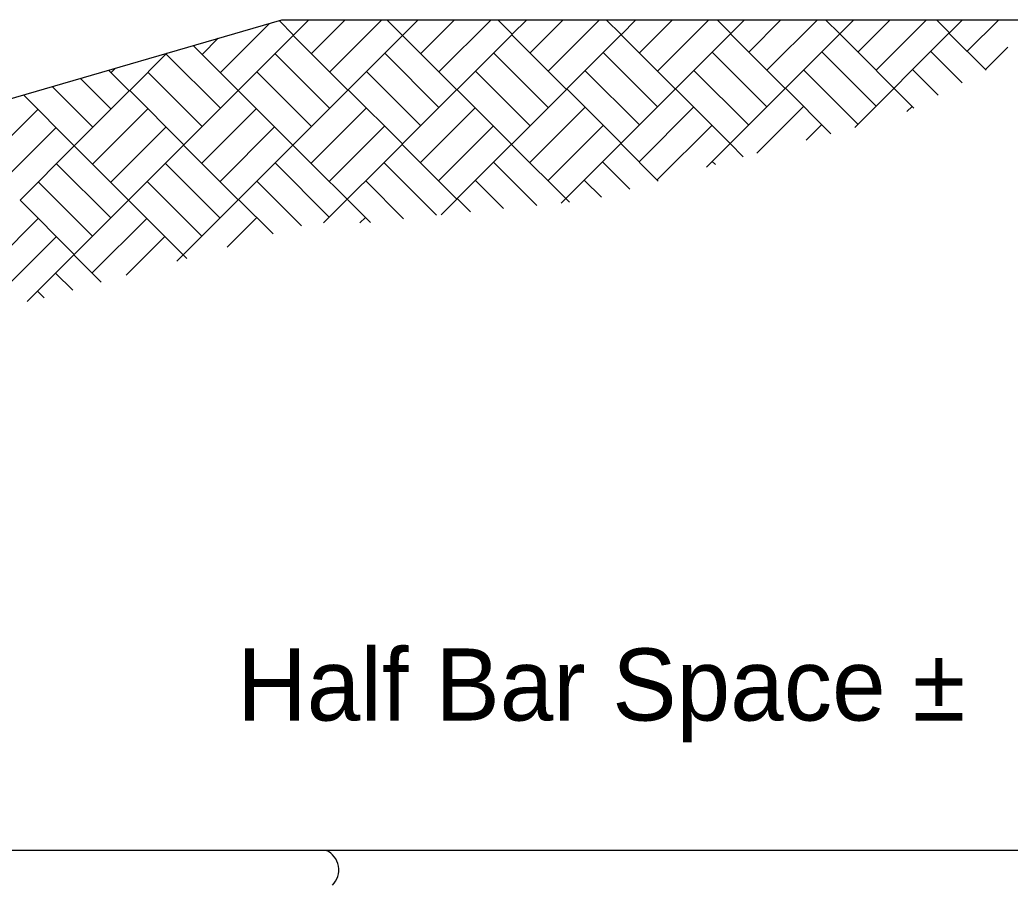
# Model space of a CAD drawing. Extents: x 0 to 221, y -2 to 90.
# Drawn here: x 46.22 to 54.52, y 25.31 to 32.56 of the extents above; entities that cross this region are included whole.
import ezdxf

# ---------------------------------------------------------------- set-up
doc = ezdxf.new("R2010")
doc.units = 0
for name, color, linetype in [('AdhocPoint_dp', 7, 'Continuous'), ('Border', 7, 'Continuous'), ('Miscellaneous', 7, 'Continuous'), ('PlotBorder_dp', 7, 'Continuous'), ('WallConc', 7, 'Continuous')]:
    doc.layers.add(name, color=color, linetype=linetype)

msp = doc.modelspace()

# ---------------------------------------------------------------- linework, layer by layer
at = {"layer": 'Border'}
for p, q in [((48.6425, 32.5647), (48.5146, 32.4368)), ((48.6425, 32.5647), (48.5146, 32.4368)), ((48.6425, 32.5647), (48.5146, 32.4368)), ((48.948, 32.5647), (48.6673, 32.2841)), ((48.948, 32.5647), (48.6673, 32.2841)), ((48.948, 32.5647), (48.6673, 32.2841)), ((49.2534, 32.5647), (48.82, 32.1313)), ((49.2534, 32.5647), (48.82, 32.1313)), ((49.2534, 32.5647), (48.82, 32.1313)), ((49.4279, 32.4337), (49.297, 32.5647)), ((49.4279, 32.4337), (49.297, 32.5647)), ((49.4279, 32.4337), (49.297, 32.5647)), ((49.5591, 32.5647), (49.428, 32.4336)), ((49.5591, 32.5647), (49.428, 32.4336)), ((49.5591, 32.5647), (49.428, 32.4336)), ((49.8646, 32.5647), (49.5808, 32.2809)), ((49.8646, 32.5647), (49.5808, 32.2809)), ((49.8646, 32.5647), (49.5808, 32.2809)), ((50.17, 32.5647), (49.7335, 32.1282)), ((50.17, 32.5647), (49.7335, 32.1282)), ((50.17, 32.5647), (49.7335, 32.1282)), ((50.3479, 32.4432), (50.2264, 32.5647)), ((50.3479, 32.4432), (50.2264, 32.5647)), ((50.3479, 32.4432), (50.2264, 32.5647)), ((50.4694, 32.5647), (50.3479, 32.4432)), ((50.4694, 32.5647), (50.3479, 32.4432)), ((50.4694, 32.5647), (50.3479, 32.4432)), ((50.7749, 32.5647), (50.5006, 32.2905)), ((50.7749, 32.5647), (50.5006, 32.2905)), ((50.7749, 32.5647), (50.5006, 32.2905)), ((51.0803, 32.5647), (50.6533, 32.1377)), ((51.0803, 32.5647), (50.6533, 32.1377)), ((51.0803, 32.5647), (50.6533, 32.1377)), ((51.2612, 32.4401), (51.1367, 32.5647)), ((51.2612, 32.4401), (51.1367, 32.5647)), ((51.2612, 32.4401), (51.1367, 32.5647)), ((51.386, 32.5647), (51.2613, 32.44)), ((51.386, 32.5647), (51.2613, 32.44)), ((51.386, 32.5647), (51.2613, 32.44)), ((51.6914, 32.5647), (51.4141, 32.2873)), ((51.6914, 32.5647), (51.4141, 32.2873)), ((51.6914, 32.5647), (51.4141, 32.2873)), ((51.9969, 32.5647), (51.5668, 32.1346)), ((51.9969, 32.5647), (51.5668, 32.1346)), ((51.9969, 32.5647), (51.5668, 32.1346)), ((52.1812, 32.4496), (52.0661, 32.5647)), ((52.1812, 32.4496), (52.0661, 32.5647)), ((52.1812, 32.4496), (52.0661, 32.5647)), ((52.2963, 32.5647), (52.1812, 32.4496)), ((52.2963, 32.5647), (52.1812, 32.4496)), ((52.2963, 32.5647), (52.1812, 32.4496)), ((52.6017, 32.5647), (52.3339, 32.2969)), ((52.6017, 32.5647), (52.3339, 32.2969)), ((52.6017, 32.5647), (52.3339, 32.2969)), ((52.9072, 32.5647), (52.4866, 32.1441)), ((52.9072, 32.5647), (52.4866, 32.1441)), ((52.9072, 32.5647), (52.4866, 32.1441)), ((53.0945, 32.4465), (52.9764, 32.5647)), ((53.0945, 32.4465), (52.9764, 32.5647)), ((53.0945, 32.4465), (52.9764, 32.5647)), ((53.2129, 32.5647), (53.0946, 32.4464)), ((53.2129, 32.5647), (53.0946, 32.4464)), ((53.2129, 32.5647), (53.0946, 32.4464)), ((53.5183, 32.5647), (53.2474, 32.2937)), ((53.5183, 32.5647), (53.2474, 32.2937)), ((53.5183, 32.5647), (53.2474, 32.2937)), ((53.8238, 32.5647), (53.4001, 32.141)), ((53.8238, 32.5647), (53.4001, 32.141)), ((53.8238, 32.5647), (53.4001, 32.141)), ((54.0145, 32.456), (53.9058, 32.5647)), ((54.0145, 32.456), (53.9058, 32.5647)), ((54.0145, 32.456), (53.9058, 32.5647)), ((54.1232, 32.5647), (54.0145, 32.456)), ((54.1232, 32.5647), (54.0145, 32.456)), ((54.1232, 32.5647), (54.0145, 32.456)), ((54.4286, 32.5647), (54.1672, 32.3033)), ((54.4286, 32.5647), (54.1672, 32.3033)), ((54.4286, 32.5647), (54.1672, 32.3033)), ((48.3134, 32.535), (47.9002, 32.1218)), ((48.3134, 32.535), (47.9002, 32.1218)), ((48.3134, 32.535), (47.9002, 32.1218)), ((48.5146, 32.4368), (48.3932, 32.5582)), ((48.5146, 32.4368), (48.3932, 32.5582)), ((48.5146, 32.4368), (48.3932, 32.5582)), ((48.5111, 32.4334), (47.5947, 31.5169)), ((48.5111, 32.4334), (47.5947, 31.5169)), ((48.5111, 32.4334), (47.5947, 31.5169)), ((47.8826, 32.4097), (47.7475, 32.2745)), ((47.8826, 32.4097), (47.7475, 32.2745)), ((47.8826, 32.4097), (47.7475, 32.2745)), ((48.5111, 32.4334), (48.9693, 31.9751)), ((48.5111, 32.4334), (48.9693, 31.9751)), ((48.5111, 32.4334), (48.9693, 31.9751)), ((49.4279, 32.4337), (48.9728, 31.9786)), ((49.4279, 32.4337), (48.9728, 31.9786)), ((49.4279, 32.4337), (48.9728, 31.9786)), ((50.3444, 32.4398), (49.428, 31.5233)), ((50.3444, 32.4398), (49.428, 31.5233)), ((50.3444, 32.4398), (49.428, 31.5233)), ((50.3414, 31.5203), (49.428, 32.4336)), ((50.3414, 31.5203), (49.428, 32.4336)), ((50.3414, 31.5203), (49.428, 32.4336)), ((50.3444, 32.4398), (50.8026, 31.9815)), ((50.3444, 32.4398), (50.8026, 31.9815)), ((50.3444, 32.4398), (50.8026, 31.9815)), ((51.2612, 32.4401), (50.8061, 31.985)), ((51.2612, 32.4401), (50.8061, 31.985)), ((51.2612, 32.4401), (50.8061, 31.985)), ((52.1777, 32.4462), (51.2613, 31.5297)), ((52.1777, 32.4462), (51.2613, 31.5297)), ((52.1777, 32.4462), (51.2613, 31.5297)), ((52.1747, 31.5267), (51.2613, 32.44)), ((52.1747, 31.5267), (51.2613, 32.44)), ((52.1747, 31.5267), (51.2613, 32.44)), ((52.1777, 32.4462), (52.6359, 31.9879)), ((52.1777, 32.4462), (52.6359, 31.9879)), ((52.1777, 32.4462), (52.6359, 31.9879)), ((53.0945, 32.4465), (52.6394, 31.9914)), ((53.0945, 32.4465), (52.6394, 31.9914)), ((53.0945, 32.4465), (52.6394, 31.9914)), ((53.7164, 31.8247), (53.0946, 32.4464)), ((53.7164, 31.8247), (53.0946, 32.4464)), ((53.7164, 31.8247), (53.0946, 32.4464)), ((54.011, 32.4526), (53.2202, 31.6617)), ((54.011, 32.4526), (53.2202, 31.6617)), ((54.011, 32.4526), (53.2202, 31.6617)), ((54.011, 32.4526), (54.3226, 32.141)), ((54.011, 32.4526), (54.3226, 32.141)), ((54.011, 32.4526), (54.3226, 32.141)), ((48.5081, 31.5139), (47.6732, 32.3487)), ((48.5081, 31.5139), (47.6732, 32.3487)), ((48.5081, 31.5139), (47.6732, 32.3487)), ((54.505, 32.3355), (54.3199, 32.1505)), ((54.505, 32.3355), (54.3199, 32.1505)), ((54.505, 32.3355), (54.3199, 32.1505)), ((47.4516, 32.2843), (47.1395, 31.9722)), ((47.4516, 32.2843), (47.1395, 31.9722)), ((47.4516, 32.2843), (47.1395, 31.9722)), ((47.9002, 31.8224), (47.445, 32.2776)), ((47.9002, 31.8224), (47.445, 32.2776)), ((47.9002, 31.8224), (47.445, 32.2776)), ((48.3584, 32.2806), (48.8166, 31.8224)), ((48.3584, 32.2806), (48.8166, 31.8224)), ((48.3584, 32.2806), (48.8166, 31.8224)), ((49.7335, 31.8288), (49.2783, 32.284)), ((49.7335, 31.8288), (49.2783, 32.284)), ((49.7335, 31.8288), (49.2783, 32.284)), ((50.1917, 32.287), (50.6499, 31.8288)), ((50.1917, 32.287), (50.6499, 31.8288)), ((50.1917, 32.287), (50.6499, 31.8288)), ((51.5668, 31.8352), (51.1116, 32.2904)), ((51.5668, 31.8352), (51.1116, 32.2904)), ((51.5668, 31.8352), (51.1116, 32.2904)), ((52.025, 32.2934), (52.4832, 31.8352)), ((52.025, 32.2934), (52.4832, 31.8352)), ((52.025, 32.2934), (52.4832, 31.8352)), ((53.4001, 31.8416), (52.9449, 32.2968)), ((53.4001, 31.8416), (52.9449, 32.2968)), ((53.4001, 31.8416), (52.9449, 32.2968)), ((53.8583, 32.2998), (54.1219, 32.0363)), ((53.8583, 32.2998), (54.1219, 32.0363)), ((53.8583, 32.2998), (54.1219, 32.0363)), ((47.0208, 32.1589), (46.9868, 32.1249)), ((47.0208, 32.1589), (46.9868, 32.1249)), ((47.0208, 32.1589), (46.9868, 32.1249)), ((53.7056, 32.1471), (53.9211, 31.9315)), ((53.7056, 32.1471), (53.9211, 31.9315)), ((53.7056, 32.1471), (53.9211, 31.9315)), ((46.7261, 32.0732), (46.9833, 31.816)), ((46.7261, 32.0732), (46.9833, 31.816)), ((46.7261, 32.0732), (46.9833, 31.816)), ((46.9627, 32.1421), (47.136, 31.9687)), ((46.9627, 32.1421), (47.136, 31.9687)), ((46.9627, 32.1421), (47.136, 31.9687)), ((47.7475, 31.6697), (47.2923, 32.1248)), ((47.7475, 31.6697), (47.2923, 32.1248)), ((47.7475, 31.6697), (47.2923, 32.1248)), ((48.2057, 32.1279), (48.6639, 31.6697)), ((48.2057, 32.1279), (48.6639, 31.6697)), ((48.2057, 32.1279), (48.6639, 31.6697)), ((49.5808, 31.6761), (49.1256, 32.1312)), ((49.5808, 31.6761), (49.1256, 32.1312)), ((49.5808, 31.6761), (49.1256, 32.1312)), ((50.039, 32.1343), (50.4972, 31.6761)), ((50.039, 32.1343), (50.4972, 31.6761)), ((50.039, 32.1343), (50.4972, 31.6761)), ((51.4141, 31.6825), (50.9589, 32.1376)), ((51.4141, 31.6825), (50.9589, 32.1376)), ((51.4141, 31.6825), (50.9589, 32.1376)), ((51.8723, 32.1407), (52.3305, 31.6825)), ((51.8723, 32.1407), (52.3305, 31.6825)), ((51.8723, 32.1407), (52.3305, 31.6825)), ((53.2474, 31.6889), (52.7922, 32.144)), ((53.2474, 31.6889), (52.7922, 32.144)), ((53.2474, 31.6889), (52.7922, 32.144)), ((46.4895, 32.0044), (46.8306, 31.6633)), ((46.4895, 32.0044), (46.8306, 31.6633)), ((46.4895, 32.0044), (46.8306, 31.6633)), ((50.8027, 31.9815), (50.3415, 31.5202)), ((50.8027, 31.9815), (50.3415, 31.5202)), ((50.8027, 31.9815), (50.3415, 31.5202)), ((51.2613, 31.5297), (50.8062, 31.9849)), ((51.2613, 31.5297), (50.8062, 31.9849)), ((51.2613, 31.5297), (50.8062, 31.9849)), ((52.636, 31.9879), (52.1748, 31.5266)), ((52.636, 31.9879), (52.1748, 31.5266)), ((52.636, 31.9879), (52.1748, 31.5266)), ((53.0214, 31.6094), (52.6395, 31.9913)), ((53.0214, 31.6094), (52.6395, 31.9913)), ((53.0214, 31.6094), (52.6395, 31.9913)), ((46.6748, 31.5075), (46.2481, 31.9342)), ((46.6748, 31.5075), (46.2481, 31.9342)), ((46.6748, 31.5075), (46.2481, 31.9342)), ((47.1361, 31.9687), (46.6749, 31.5074)), ((47.1361, 31.9687), (46.6749, 31.5074)), ((47.1361, 31.9687), (46.6749, 31.5074)), ((47.5947, 31.5169), (47.1396, 31.9721)), ((47.5947, 31.5169), (47.1396, 31.9721)), ((47.5947, 31.5169), (47.1396, 31.9721)), ((48.9694, 31.9751), (48.5082, 31.5138)), ((48.9694, 31.9751), (48.5082, 31.5138)), ((48.9694, 31.9751), (48.5082, 31.5138)), ((49.428, 31.5233), (48.9729, 31.9785)), ((49.428, 31.5233), (48.9729, 31.9785)), ((49.428, 31.5233), (48.9729, 31.9785)), ((47.2889, 31.8159), (46.8276, 31.3547)), ((47.2889, 31.8159), (46.8276, 31.3547)), ((47.2889, 31.8159), (46.8276, 31.3547)), ((48.2026, 31.8194), (47.7475, 31.3642)), ((48.2026, 31.8194), (47.7475, 31.3642)), ((48.2026, 31.8194), (47.7475, 31.3642)), ((49.1222, 31.8223), (48.6609, 31.3611)), ((49.1222, 31.8223), (48.6609, 31.3611)), ((49.1222, 31.8223), (48.6609, 31.3611)), ((50.0359, 31.8258), (49.5808, 31.3706)), ((50.0359, 31.8258), (49.5808, 31.3706)), ((50.0359, 31.8258), (49.5808, 31.3706)), ((50.9555, 31.8287), (50.4942, 31.3675)), ((50.9555, 31.8287), (50.4942, 31.3675)), ((50.9555, 31.8287), (50.4942, 31.3675)), ((51.8692, 31.8322), (51.4141, 31.377)), ((51.8692, 31.8322), (51.4141, 31.377)), ((51.8692, 31.8322), (51.4141, 31.377)), ((52.7888, 31.8351), (52.3993, 31.4457)), ((52.7888, 31.8351), (52.3993, 31.4457)), ((52.7888, 31.8351), (52.3993, 31.4457)), ((53.7025, 31.8386), (53.6584, 31.7944)), ((53.7025, 31.8386), (53.6584, 31.7944)), ((53.7025, 31.8386), (53.6584, 31.7944)), ((46.3693, 31.813), (45.9142, 31.3578)), ((46.3693, 31.813), (45.9142, 31.3578)), ((46.3693, 31.813), (45.9142, 31.3578)), ((46.5221, 31.6602), (46.0669, 31.2051)), ((46.5221, 31.6602), (46.0669, 31.2051)), ((46.5221, 31.6602), (46.0669, 31.2051)), ((47.4416, 31.6632), (46.9804, 31.2019)), ((47.4416, 31.6632), (46.9804, 31.2019)), ((47.4416, 31.6632), (46.9804, 31.2019)), ((48.3553, 31.6666), (47.9002, 31.2115)), ((48.3553, 31.6666), (47.9002, 31.2115)), ((48.3553, 31.6666), (47.9002, 31.2115)), ((49.2749, 31.6696), (48.8136, 31.2083)), ((49.2749, 31.6696), (48.8136, 31.2083)), ((49.2749, 31.6696), (48.8136, 31.2083)), ((50.1886, 31.673), (49.7335, 31.2179)), ((50.1886, 31.673), (49.7335, 31.2179)), ((50.1886, 31.673), (49.7335, 31.2179)), ((51.1082, 31.676), (50.6469, 31.2147)), ((51.1082, 31.676), (50.6469, 31.2147)), ((51.1082, 31.676), (50.6469, 31.2147)), ((52.0219, 31.6794), (51.5668, 31.2243)), ((52.0219, 31.6794), (51.5668, 31.2243)), ((52.0219, 31.6794), (51.5668, 31.2243)), ((52.9415, 31.6824), (52.8139, 31.5548)), ((52.9415, 31.6824), (52.8139, 31.5548)), ((52.9415, 31.6824), (52.8139, 31.5548)), ((46.6748, 31.5075), (46.2196, 31.0523)), ((46.6748, 31.5075), (46.2196, 31.0523)), ((46.6748, 31.5075), (46.2196, 31.0523)), ((47.5913, 31.5135), (46.6749, 30.5971)), ((47.5913, 31.5135), (46.6749, 30.5971)), ((47.5913, 31.5135), (46.6749, 30.5971)), ((47.5882, 30.594), (46.6749, 31.5074)), ((47.5882, 30.594), (46.6749, 31.5074)), ((47.5882, 30.594), (46.6749, 31.5074)), ((47.5913, 31.5135), (48.0495, 31.0553)), ((47.5913, 31.5135), (48.0495, 31.0553)), ((47.5913, 31.5135), (48.0495, 31.0553)), ((48.5081, 31.5139), (48.0529, 31.0587)), ((48.5081, 31.5139), (48.0529, 31.0587)), ((48.5081, 31.5139), (48.0529, 31.0587)), ((49.1582, 30.8637), (48.5082, 31.5138)), ((49.1582, 30.8637), (48.5082, 31.5138)), ((49.1582, 30.8637), (48.5082, 31.5138)), ((49.4246, 31.5199), (48.7653, 30.8606)), ((49.4246, 31.5199), (48.7653, 30.8606)), ((49.4246, 31.5199), (48.7653, 30.8606)), ((49.4246, 31.5199), (49.8828, 31.0617)), ((49.4246, 31.5199), (49.8828, 31.0617)), ((49.4246, 31.5199), (49.8828, 31.0617)), ((50.3414, 31.5203), (49.8862, 31.0651)), ((50.3414, 31.5203), (49.8862, 31.0651)), ((50.3414, 31.5203), (49.8862, 31.0651)), ((50.827, 31.0347), (50.3415, 31.5202)), ((50.827, 31.0347), (50.3415, 31.5202)), ((50.827, 31.0347), (50.3415, 31.5202)), ((51.2579, 31.5263), (50.7597, 31.0281)), ((51.2579, 31.5263), (50.7597, 31.0281)), ((51.2579, 31.5263), (50.7597, 31.0281)), ((51.2579, 31.5263), (51.5716, 31.2126)), ((51.2579, 31.5263), (51.5716, 31.2126)), ((51.2579, 31.5263), (51.5716, 31.2126)), ((52.1747, 31.5267), (51.9762, 31.3282)), ((52.1747, 31.5267), (51.9762, 31.3282)), ((52.1747, 31.5267), (51.9762, 31.3282)), ((52.2856, 31.4158), (52.1748, 31.5266)), ((52.2856, 31.4158), (52.1748, 31.5266)), ((52.2856, 31.4158), (52.1748, 31.5266)), ((46.9804, 30.9026), (46.5252, 31.3577)), ((46.9804, 30.9026), (46.5252, 31.3577)), ((46.9804, 30.9026), (46.5252, 31.3577)), ((47.4386, 31.3608), (47.8968, 30.9026)), ((47.4386, 31.3608), (47.8968, 30.9026)), ((47.4386, 31.3608), (47.8968, 30.9026)), ((48.8136, 30.909), (48.3585, 31.3641)), ((48.8136, 30.909), (48.3585, 31.3641)), ((48.8136, 30.909), (48.3585, 31.3641)), ((49.2719, 31.3672), (49.713, 30.926)), ((49.2719, 31.3672), (49.713, 30.926)), ((49.2719, 31.3672), (49.713, 30.926)), ((50.5542, 31.0081), (50.1918, 31.3705)), ((50.5542, 31.0081), (50.1918, 31.3705)), ((50.5542, 31.0081), (50.1918, 31.3705)), ((51.1051, 31.3736), (51.334, 31.1447)), ((51.1051, 31.3736), (51.334, 31.1447)), ((51.1051, 31.3736), (51.334, 31.1447)), ((52.0521, 31.3499), (52.0251, 31.3769)), ((52.0521, 31.3499), (52.0251, 31.3769)), ((52.0521, 31.3499), (52.0251, 31.3769)), ((46.8276, 30.7498), (46.3725, 31.205)), ((46.8276, 30.7498), (46.3725, 31.205)), ((46.8276, 30.7498), (46.3725, 31.205)), ((47.2858, 31.208), (47.744, 30.7498)), ((47.2858, 31.208), (47.744, 30.7498)), ((47.2858, 31.208), (47.744, 30.7498)), ((48.5795, 30.8377), (48.2058, 31.2114)), ((48.5795, 30.8377), (48.2058, 31.2114)), ((48.5795, 30.8377), (48.2058, 31.2114)), ((49.1191, 31.2144), (49.437, 30.8965)), ((49.1191, 31.2144), (49.437, 30.8965)), ((49.1191, 31.2144), (49.437, 30.8965)), ((50.2759, 30.9809), (50.0391, 31.2178)), ((50.2759, 30.9809), (50.0391, 31.2178)), ((50.2759, 30.9809), (50.0391, 31.2178)), ((50.9524, 31.2208), (51.0964, 31.0768)), ((50.9524, 31.2208), (51.0964, 31.0768)), ((50.9524, 31.2208), (51.0964, 31.0768)), ((46.6749, 30.5971), (46.2197, 31.0522)), ((46.6749, 30.5971), (46.2197, 31.0522)), ((46.6749, 30.5971), (46.2197, 31.0522)), ((48.0496, 31.0552), (47.5883, 30.5939)), ((48.0496, 31.0552), (47.5883, 30.5939)), ((48.0496, 31.0552), (47.5883, 30.5939)), ((48.3428, 30.7688), (48.053, 31.0586)), ((48.3428, 30.7688), (48.053, 31.0586)), ((48.3428, 30.7688), (48.053, 31.0586)), ((49.8829, 31.0616), (49.751, 30.9297)), ((49.8829, 31.0616), (49.751, 30.9297)), ((49.8829, 31.0616), (49.751, 30.9297)), ((49.9976, 30.9538), (49.8863, 31.065)), ((49.9976, 30.9538), (49.8863, 31.065)), ((49.9976, 30.9538), (49.8863, 31.065)), ((48.2023, 30.9025), (47.9574, 30.6576)), ((48.2023, 30.9025), (47.9574, 30.6576)), ((48.2023, 30.9025), (47.9574, 30.6576)), ((49.1161, 30.9059), (49.0708, 30.8606)), ((49.1161, 30.9059), (49.0708, 30.8606)), ((49.1161, 30.9059), (49.0708, 30.8606)), ((46.369, 30.8961), (45.9078, 30.4348)), ((46.369, 30.8961), (45.9078, 30.4348)), ((46.369, 30.8961), (45.9078, 30.4348)), ((47.2828, 30.8995), (46.8276, 30.4444)), ((47.2828, 30.8995), (46.8276, 30.4444)), ((47.2828, 30.8995), (46.8276, 30.4444)), ((46.5218, 30.7433), (46.0605, 30.2821)), ((46.5218, 30.7433), (46.0605, 30.2821)), ((46.5218, 30.7433), (46.0605, 30.2821)), ((47.4355, 30.7468), (47.1113, 30.4225)), ((47.4355, 30.7468), (47.1113, 30.4225)), ((47.4355, 30.7468), (47.1113, 30.4225)), ((46.6714, 30.5937), (46.2799, 30.2021)), ((46.6714, 30.5937), (46.2799, 30.2021)), ((46.6714, 30.5937), (46.2799, 30.2021)), ((46.6714, 30.5937), (46.901, 30.3641)), ((46.6714, 30.5937), (46.901, 30.3641)), ((46.6714, 30.5937), (46.901, 30.3641)), ((47.5882, 30.594), (47.5342, 30.54)), ((47.5882, 30.594), (47.5342, 30.54)), ((47.5882, 30.594), (47.5342, 30.54)), ((47.6188, 30.5635), (47.5883, 30.5939)), ((47.6188, 30.5635), (47.5883, 30.5939)), ((47.6188, 30.5635), (47.5883, 30.5939)), ((46.5187, 30.4409), (46.6619, 30.2977)), ((46.5187, 30.4409), (46.6619, 30.2977)), ((46.5187, 30.4409), (46.6619, 30.2977)), ((46.366, 30.2882), (46.4213, 30.2329)), ((46.366, 30.2882), (46.4213, 30.2329)), ((46.366, 30.2882), (46.4213, 30.2329))]:
    msp.add_line(p, q, dxfattribs=at)
at = {"layer": 'Miscellaneous'}
for p, q in [((27.165, 26.3827), (48.4156, 32.5647)), ((48.4156, 32.5647), (65.6946, 32.5647))]:
    msp.add_line(p, q, dxfattribs=at)
at = {"layer": 'PlotBorder_dp'}
msp.add_arc((48.7148, 25.4345), 0.1788, 314.1793, 65.90652, dxfattribs=at)
at = {"layer": 'WallConc'}
msp.add_line((56.8728, 25.5979), (27.165, 25.5979), dxfattribs=at)

# ---------------------------------------------------------------- texts
at = {"layer": 'AdhocPoint_dp'}
msp.add_text('Half Bar Space ±', height=0.604801, dxfattribs=at).set_placement((48.0407, 26.6873))

doc.saveas('drawing.dxf')
